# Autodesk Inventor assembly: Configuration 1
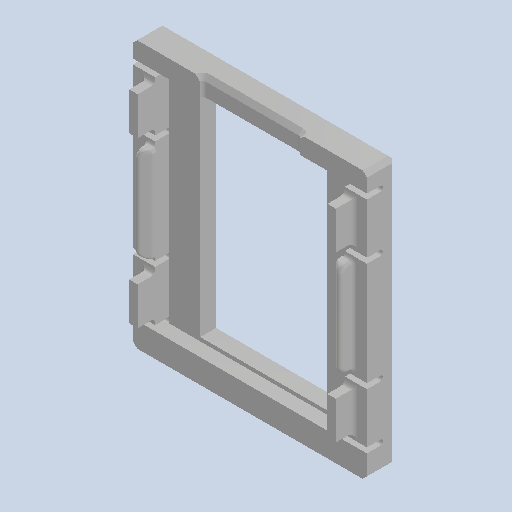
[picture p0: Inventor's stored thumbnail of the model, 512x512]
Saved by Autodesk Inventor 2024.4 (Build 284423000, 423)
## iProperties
Created: 2025-05
Part Number: Configuration 1
Document SubType Name: Assembly
Designer: AdminForWorker
Title: XIAO-ESP32S3-Sense-housing-design(bottom) v4
Author: AdminForWorker
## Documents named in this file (2)
- c:\worker\convert-fusion-r02-cosv3\tmp\job-1\2\temp\files\be827049-a7f2-47ea-a815-8d9efd6bfce9\XIAO-ESP32S3-Sense-housing-design(bottom) v4.iam
- c:\worker\convert-fusion-r02-cosv3\tmp\job-1\2\temp\files\be827049-a7f2-47ea-a815-8d9efd6bfce9\Part2.ipt
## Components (1 placed, 1 different names)
1. Part2
